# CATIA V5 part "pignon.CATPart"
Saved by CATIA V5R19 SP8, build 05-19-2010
Part number: pignon
Revision: ANY
Definition: UNKNOWN
Nomenclature: 23
Source: Unknown
Bounding box of the stored display mesh (mm): x -4.863 to 4.863, y -4.869 to 4.786, z 0 to 8
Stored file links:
  D:\Documents\1_Travail\2- 2I2D\1 - Cours et TD\2- TD\3-TD Assemblage\Pompe AirMan\pignon.CATPart
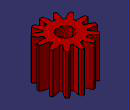
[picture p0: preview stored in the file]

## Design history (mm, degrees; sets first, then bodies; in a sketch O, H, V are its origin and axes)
Body1 "Répétition circulaire1" (main body)
  Solid1: solid without history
